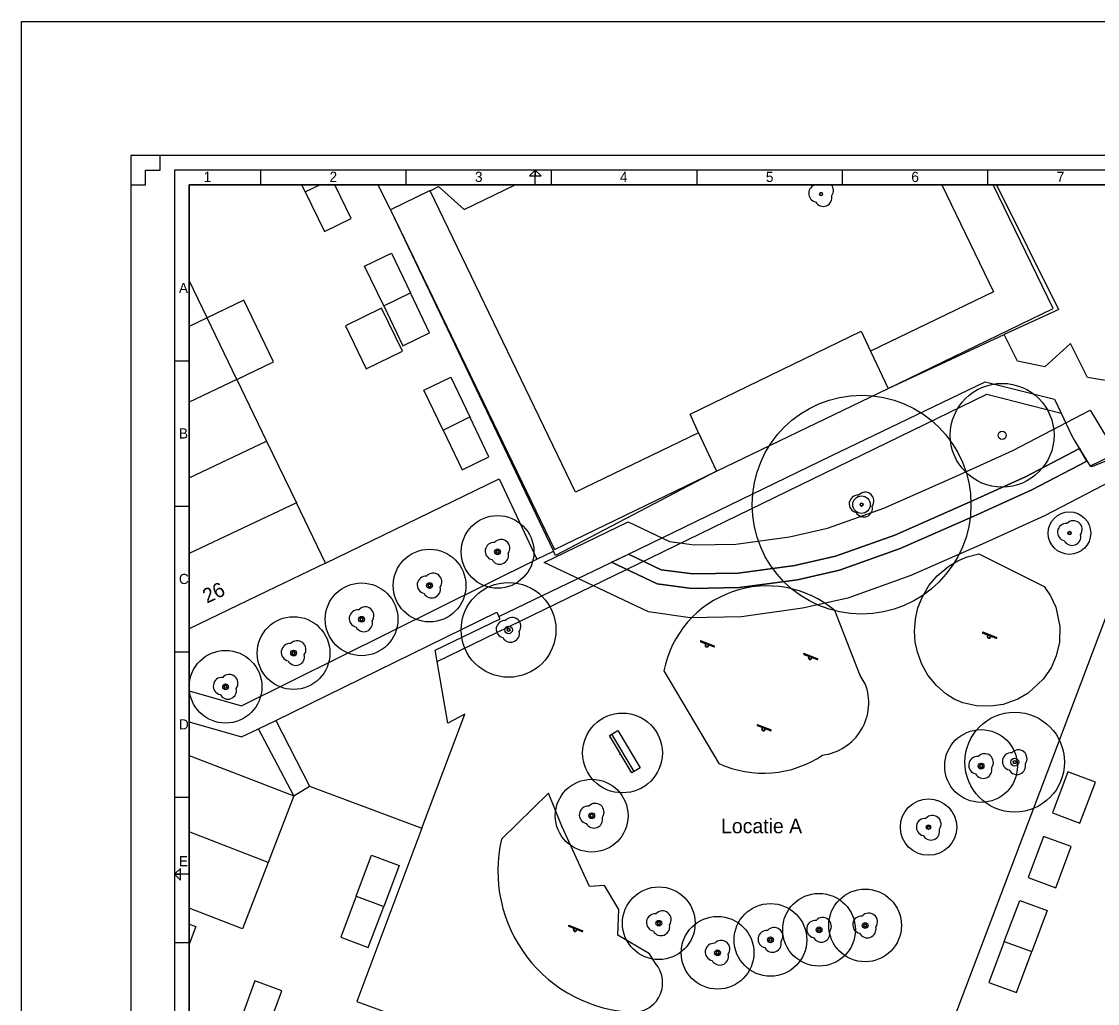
# Model space of a CAD drawing. Extents: x 192664 to 192925, y 446334 to 446521.
# Drawn here: x 192664.2 to 192738.2, y 446453.5 to 446521 of the extents above; entities that cross this region are included whole.
import ezdxf

# ---------------------------------------------------------------- set-up
doc = ezdxf.new("R2010")
doc.units = 0
for name, color, linetype in [('( Toegevoegd 29-11-2021 14_41_42) grens IMGEO maaiveld', 7, 'Continuous'), ('( Toegevoegd 29-11-2021 14_41_42) wegdeel vlak', 7, 'Continuous'), ('1010 viewport', 7, 'Continuous'), ('B-GV-GR-BOOM-S', 7, 'Continuous'), ('B-GV-KG-GRENS_WERKGRENS-G', 7, 'Continuous'), ('boom', 7, 'Continuous'), ('Cultuurscheiding grens', 7, 'Continuous'), ('grens maaiveld', 7, 'Continuous'), ('huisnummerreeks BGT', 7, 'Continuous'), ('kant open verharding', 7, 'Continuous'), ('Luifel', 7, 'Continuous'), ('N-GV-IE-MEUBILAIR_WEGMEUBILAIR_ZITBANK-S', 7, 'Continuous'), ('N-GV-VH-VERHARDING_HALFVERHARDING-G', 7, 'Continuous'), ('pand op maaiveld vlak', 7, 'Continuous'), ('speelvoorziening', 7, 'Continuous'), ('TEKST', 7, 'Continuous'), ('X-XX-AL-TEKENBLAD-S', 7, 'Continuous'), ('X-XX-AL-TEKENBLAD_KADER-G', 7, 'Continuous')]:
    doc.layers.add(name, color=color, linetype=linetype)

msp = doc.modelspace()

# ---------------------------------------------------------------- linework, layer by layer
at = {"layer": '( Toegevoegd 29-11-2021 14_41_42) grens IMGEO maaiveld'}
for points in [[(192692.796, 446476.982), (192700.21, 446480.586), (192706.619, 446483.701), (192730.589, 446495.348), (192735.697, 446494.05)], [(192692.796, 446476.982), (192692.679, 446477.648), (192692.661, 446477.75), (192697.119, 446479.917), (192697.041, 446480.077)]]:
    msp.add_lwpolyline(points, dxfattribs=at)
at = {"layer": '( Toegevoegd 29-11-2021 14_41_42) wegdeel vlak'}
for p, q in [((192723.799, 446495.758), (192731.791, 446499.455)), ((192699.659, 446484.024), (192700.805, 446484.559)), ((192680.513, 446472.341), (192681.713, 446472.935))]:
    msp.add_line(p, q, dxfattribs=at)
for points in [[(192765.561, 446498.667), (192758.023, 446494.654), (192749.243, 446494.562), (192737.517, 446496.509), (192736.353, 446498.833), (192734.578, 446497.242), (192732.701, 446497.637), (192731.791, 446499.455)], [(192697.041, 446480.077), (192705.946, 446484.365), (192719.886, 446491.112), (192730.483, 446496.207), (192735.246, 446495.022), (192735.697, 446494.05)], [(192735.697, 446494.05), (192736.404, 446492.528), (192736.642, 446492.136), (192737.693, 446490.405)], [(192747.709, 446492.058), (192744.573, 446493.06), (192743.573, 446493.255), (192737.693, 446490.405)], [(192712.011, 446490.054), (192700.942, 446484.272), (192700.805, 446484.559)], [(192675.743, 446474.958), (192679.338, 446473.942), (192699.659, 446484.024)], [(192681.713, 446472.935), (192696.889, 446480.371), (192697.041, 446480.077)], [(192675.743, 446472.827), (192679.351, 446471.8), (192680.513, 446472.341)]]:
    msp.add_lwpolyline(points, dxfattribs=at)
at = {"layer": '1010 viewport'}
msp.add_lwpolyline([(192675.743, 446509.756), (192860.643, 446509.756), (192860.643, 446345.556), (192675.743, 446345.556)], close=True, dxfattribs=at)
at = {"layer": 'B-GV-GR-BOOM-S'}
for centre, radius in [((192731.644, 446492.531), 3.567), ((192721.977, 446487.765), 7.524), ((192731.644, 446492.531), 0.285), ((192721.977, 446487.765), 0.602), ((192696.948, 446484.518), 2.5), ((192736.27, 446485.807), 1.46), ((192736.27, 446485.807), 0.117), ((192692.274, 446482.199), 2.5), ((192696.948, 446484.518), 0.2), ((192692.274, 446482.199), 0.2), ((192697.706, 446479.154), 3.258), ((192687.6, 446479.88), 2.5), ((192682.926, 446477.561), 2.5), ((192687.6, 446479.88), 0.2), ((192697.706, 446479.154), 0.261), ((192678.252, 446475.242), 2.5), ((192682.926, 446477.561), 0.2), ((192678.252, 446475.242), 0.2), ((192732.506, 446470.06), 3.428), ((192730.192, 446469.795), 2.5), ((192730.192, 446469.795), 0.2), ((192732.506, 446470.06), 0.274), ((192703.422, 446466.38), 2.5), ((192726.584, 446465.596), 1.938), ((192703.422, 446466.38), 0.2), ((192726.584, 446465.596), 0.155), ((192708.038, 446458.986), 2.5), ((192719.053, 446458.537), 2.5), ((192722.223, 446458.835), 2.5), ((192715.712, 446457.845), 2.5), ((192712.077, 446456.959), 2.5), ((192708.038, 446458.986), 0.2), ((192719.053, 446458.537), 0.2), ((192722.223, 446458.835), 0.2), ((192715.712, 446457.845), 0.2), ((192712.077, 446456.959), 0.2)]:
    msp.add_circle(centre, radius, dxfattribs=at)
at = {"layer": 'B-GV-KG-GRENS_WERKGRENS-G'}
msp.add_lwpolyline([(192740.295, 446489.973), (192734.557, 446486.987), (192730.473, 446485.129), (192725.366, 446482.882), (192721.029, 446481.333), (192717.923, 446480.635), (192713.732, 446480.061), (192710.196, 446479.993), (192707.335, 446480.383), (192700.156, 446483.797), (192705.941, 446486.582), (192708.78, 446485.232), (192710.487, 446485), (192713.343, 446485.054), (192717.034, 446485.56), (192719.635, 446486.145), (192723.516, 446487.53), (192728.43, 446489.693), (192732.367, 446491.484), (192737.694, 446494.256)], close=True, dxfattribs=at)
msp.add_circle((192705.538, 446470.693), 2.743, dxfattribs=at)
at = {"layer": 'boom'}
msp.add_line((192719.898, 446509.756), (192718.831, 446509.756), dxfattribs=at)
for centre in [(192719.192, 446509.116), (192721.977, 446487.765), (192736.298, 446485.811), (192696.948, 446484.518), (192692.274, 446482.199), (192687.6, 446479.88), (192697.706, 446479.154), (192682.926, 446477.561), (192678.252, 446475.242), (192730.192, 446469.795), (192732.506, 446470.06), (192703.422, 446466.38), (192726.595, 446465.551), (192708.038, 446458.986), (192722.223, 446458.835), (192719.053, 446458.537), (192715.712, 446457.845), (192712.077, 446456.959)]:
    msp.add_circle(centre, 0.1, dxfattribs=at)
for centre, radius, start, end in [((192718.942, 446509.166), 0.6, 100.64034, 257.75442), ((192719.442, 446509.366), 0.6, 323.54458, 40.50182), ((192719.192, 446509.116), 0.1, 0, 180), ((192719.192, 446509.116), 0.1, 180, 0), ((192719.342, 446508.866), 0.6, 208.50578, 13.83556), ((192721.727, 446487.815), 0.6, 85.13702, 257.75442), ((192722.227, 446488.015), 0.6, 323.54458, 138.4658), ((192722.127, 446487.515), 0.6, 208.50578, 13.83556), ((192721.977, 446487.765), 0.1, 0, 180), ((192721.977, 446487.765), 0.1, 180, 0), ((192736.048, 446485.861), 0.6, 85.13702, 257.75442), ((192736.548, 446486.061), 0.6, 323.54458, 138.4658), ((192697.198, 446484.768), 0.6, 323.54458, 138.4658), ((192736.448, 446485.561), 0.6, 208.50578, 13.83556), ((192736.298, 446485.811), 0.1, 0, 180), ((192736.298, 446485.811), 0.1, 180, 0), ((192696.698, 446484.568), 0.6, 85.13702, 257.75442), ((192696.948, 446484.518), 0.1, 0, 180), ((192697.098, 446484.268), 0.6, 208.50578, 13.83556), ((192696.948, 446484.518), 0.1, 180, 0), ((192692.024, 446482.249), 0.6, 85.13702, 257.75442), ((192692.524, 446482.449), 0.6, 323.54458, 138.4658), ((192692.424, 446481.949), 0.6, 208.50578, 13.83556), ((192692.274, 446482.199), 0.1, 0, 180), ((192692.274, 446482.199), 0.1, 180, 0), ((192687.35, 446479.93), 0.6, 85.13702, 257.75442), ((192687.85, 446480.13), 0.6, 323.54458, 138.4658), ((192687.75, 446479.63), 0.6, 208.50578, 13.83556), ((192687.6, 446479.88), 0.1, 0, 180), ((192687.6, 446479.88), 0.1, 180, 0), ((192697.456, 446479.204), 0.6, 85.13702, 257.75442), ((192697.956, 446479.404), 0.6, 323.54458, 138.4658), ((192697.856, 446478.904), 0.6, 208.50578, 13.83556), ((192697.706, 446479.154), 0.1, 0, 180), ((192697.706, 446479.154), 0.1, 180, 0), ((192682.676, 446477.611), 0.6, 85.13702, 257.75442), ((192683.176, 446477.811), 0.6, 323.54458, 138.4658), ((192683.076, 446477.311), 0.6, 208.50578, 13.83556), ((192682.926, 446477.561), 0.1, 0, 180), ((192682.926, 446477.561), 0.1, 180, 0), ((192678.002, 446475.292), 0.6, 85.13702, 257.75442), ((192678.502, 446475.492), 0.6, 323.54458, 138.4658), ((192678.402, 446474.992), 0.6, 208.50578, 13.83556), ((192678.252, 446475.242), 0.1, 0, 180), ((192678.252, 446475.242), 0.1, 180, 0), ((192730.442, 446470.045), 0.6, 323.54458, 138.4658), ((192732.256, 446470.11), 0.6, 85.13702, 257.75442), ((192732.756, 446470.31), 0.6, 323.54458, 138.4658), ((192729.942, 446469.845), 0.6, 85.13702, 257.75442), ((192730.192, 446469.795), 0.1, 0, 180), ((192732.656, 446469.81), 0.6, 208.50578, 13.83556), ((192732.506, 446470.06), 0.1, 0, 180), ((192732.506, 446470.06), 0.1, 180, 0), ((192730.342, 446469.545), 0.6, 208.50578, 13.83556), ((192730.192, 446469.795), 0.1, 180, 0), ((192703.172, 446466.43), 0.6, 85.13702, 257.75442), ((192703.672, 446466.63), 0.6, 323.54458, 138.4658), ((192703.572, 446466.13), 0.6, 208.50578, 13.83556), ((192703.422, 446466.38), 0.1, 0, 180), ((192703.422, 446466.38), 0.1, 180, 0), ((192726.345, 446465.601), 0.6, 85.13702, 257.75442), ((192726.845, 446465.801), 0.6, 323.54458, 138.4658), ((192726.745, 446465.301), 0.6, 208.50578, 13.83556), ((192726.595, 446465.551), 0.1, 0, 180), ((192726.595, 446465.551), 0.1, 180, 0), ((192707.788, 446459.036), 0.6, 85.13702, 257.75442), ((192708.288, 446459.236), 0.6, 323.54458, 138.4658), ((192721.973, 446458.885), 0.6, 85.13702, 257.75442), ((192722.473, 446459.085), 0.6, 323.54458, 138.4658), ((192708.188, 446458.736), 0.6, 208.50578, 13.83556), ((192708.038, 446458.986), 0.1, 0, 180), ((192708.038, 446458.986), 0.1, 180, 0), ((192718.803, 446458.587), 0.6, 85.13702, 257.75442), ((192719.303, 446458.787), 0.6, 323.54458, 138.4658), ((192722.373, 446458.585), 0.6, 208.50578, 13.83556), ((192722.223, 446458.835), 0.1, 0, 180), ((192722.223, 446458.835), 0.1, 180, 0), ((192715.462, 446457.895), 0.6, 85.13702, 257.75442), ((192715.962, 446458.095), 0.6, 323.54458, 138.4658), ((192719.203, 446458.287), 0.6, 208.50578, 13.83556), ((192719.053, 446458.537), 0.1, 0, 180), ((192719.053, 446458.537), 0.1, 180, 0), ((192711.827, 446457.009), 0.6, 85.13702, 257.75442), ((192712.327, 446457.209), 0.6, 323.54458, 138.4658), ((192715.862, 446457.595), 0.6, 208.50578, 13.83556), ((192715.712, 446457.845), 0.1, 0, 180), ((192715.712, 446457.845), 0.1, 180, 0), ((192712.227, 446456.709), 0.6, 208.50578, 13.83556), ((192712.077, 446456.959), 0.1, 0, 180), ((192712.077, 446456.959), 0.1, 180, 0)]:
    msp.add_arc(centre, radius, start, end, dxfattribs=at)
at = {"layer": 'Cultuurscheiding grens'}
msp.add_lwpolyline([(192691.747, 446465.52), (192694.691, 446473.369), (192693.538, 446472.733), (192692.796, 446476.982)], dxfattribs=at)
at = {"layer": 'grens maaiveld'}
for p, q in [((192734.733, 446469.332), (192739.028, 446480.658)), ((192708.379, 446476.339), (192712.17, 446469.965)), ((192727.776, 446450.988), (192734.733, 446469.332)), ((192684.027, 446468.415), (192691.747, 446465.52))]:
    msp.add_line(p, q, dxfattribs=at)
for points in [[(192731.256, 446509.756), (192735.523, 446501.181), (192735.241, 446501.05), (192731.791, 446499.455)], [(192689.585, 446508.03), (192698.618, 446489.133), (192700.777, 446484.617), (192700.805, 446484.559)], [(192741.724, 446487.765), (192743.611, 446492.741), (192742.468, 446492.211), (192737.789, 446490.36), (192737.693, 446490.405)], [(192685.115, 446483.75), (192697.057, 446489.535), (192699.659, 446484.024)], [(192730.048, 446484.381), (192734.539, 446482.146), (192734.976, 446481.492), (192735.334, 446480.706), (192735.616, 446479.385), (192735.585, 446478.306), (192735.367, 446477.373), (192735.003, 446476.54), (192734.475, 446475.758), (192733.432, 446474.796), (192732.726, 446474.388), (192731.709, 446474.029), (192730.84, 446473.9), (192729.888, 446473.931), (192728.946, 446474.143), (192728.344, 446474.383), (192727.761, 446474.766), (192727.128, 446475.326), (192726.54, 446476.051), (192726.118, 446476.797), (192725.815, 446477.617), (192725.664, 446478.342), (192725.615, 446479.036), (192725.676, 446479.884), (192725.856, 446480.671), (192726.137, 446481.388), (192726.614, 446482.201), (192727.175, 446482.868), (192727.975, 446483.533), (192728.589, 446483.894), (192729.246, 446484.171), (192730.048, 446484.381)], [(192722.227, 446475.451), (192721.87, 446476.011), (192720.15, 446480.477)], [(192706.331, 446452.863), (192706.518, 446452.877), (192706.732, 446452.916), (192707.023, 446453.007), (192707.362, 446453.181), (192707.672, 446453.423), (192707.87, 446453.641), (192708.021, 446453.863), (192708.159, 446454.143), (192708.26, 446454.473), (192708.295, 446454.703), (192708.29, 446455.149), (192708.241, 446455.406), (192708.137, 446455.709), (192707.986, 446455.995), (192707.816, 446456.224), (192707.394, 446456.89), (192705.222, 446458.158), (192705.296, 446459.943), (192704.312, 446461.578), (192703.272, 446461.519), (192701.368, 446465.65), (192700.45, 446467.928), (192697.225, 446464.769)], [(192691.747, 446465.52), (192687.282, 446453.612), (192695.28, 446450.68)]]:
    msp.add_lwpolyline(points, dxfattribs=at)
for centre, radius, start, end in [((192715.488, 446474.927), 7.248, 49.97203, 168.76539), ((192718.848, 446474.142), 3.624, 277.09196, 21.17996), ((192715.215, 446476.613), 7.313, 245.39293, 303.9147), ((192706.69, 446462.573), 9.716, 166.93585, 267.88344)]:
    msp.add_arc(centre, radius, start, end, dxfattribs=at)
at = {"layer": 'kant open verharding'}
for p, q in [((192681.713, 446472.935), (192684.027, 446468.415)), ((192682.936, 446467.748), (192680.513, 446472.341)), ((192682.936, 446467.748), (192684.027, 446468.415))]:
    msp.add_line(p, q, dxfattribs=at)
at = {"layer": 'Luifel'}
for points in [[(192727.487, 446509.756), (192731.041, 446502.394), (192722.591, 446498.314)], [(192723.799, 446495.758), (192735.147, 446501.237), (192731.034, 446509.756)], [(192710.775, 446492.708), (192702.313, 446488.623), (192692.309, 446509.345)], [(192689.585, 446508.03), (192700.861, 446484.671), (192712.011, 446490.054)], [(192679.03, 446496.364), (192681.55, 446497.579), (192679.505, 446501.819), (192676.985, 446500.604)]]:
    msp.add_lwpolyline(points, dxfattribs=at)
at = {"layer": 'N-GV-IE-MEUBILAIR_WEGMEUBILAIR_ZITBANK-S'}
msp.add_line((192706.336, 446469.418), (192704.802, 446471.996), dxfattribs=at)
msp.add_lwpolyline([(192706.757, 446469.668), (192706.173, 446469.321), (192704.639, 446471.899), (192705.223, 446472.246)], close=True, dxfattribs=at)
for points in [[(192704.741, 446471.727), (192704.711, 446471.709), (192704.685, 446471.753), (192704.716, 446471.771)], [(192705.419, 446470.588), (192705.389, 446470.57), (192705.363, 446470.614), (192705.393, 446470.632)], [(192706.096, 446469.449), (192706.066, 446469.431), (192706.04, 446469.475), (192706.071, 446469.493)]]:
    msp.add_lwpolyline(points, dxfattribs=at)
at = {"layer": 'N-GV-VH-VERHARDING_HALFVERHARDING-G'}
for p, q in [((192737.477, 446490.761), (192736.957, 446491.618)), ((192704.789, 446483.808), (192705.946, 446484.365))]:
    msp.add_line(p, q, dxfattribs=at)
msp.add_lwpolyline([(192737.477, 446490.761), (192733.681, 446488.786), (192729.656, 446486.955), (192724.626, 446484.741), (192720.471, 446483.258), (192717.567, 446482.605), (192713.576, 446482.058), (192710.312, 446481.996), (192707.913, 446482.322), (192704.789, 446483.808), (192705.946, 446484.365), (192708.202, 446483.292), (192710.37, 446482.997), (192713.499, 446483.057), (192717.389, 446483.59), (192720.193, 446484.22), (192724.256, 446485.671), (192729.247, 446487.868), (192733.243, 446489.685), (192736.957, 446491.618)], close=True, dxfattribs=at)
for points in [[(192736.957, 446491.618), (192733.243, 446489.685), (192729.247, 446487.868), (192724.256, 446485.671), (192720.193, 446484.22), (192717.389, 446483.59), (192713.499, 446483.057), (192710.37, 446482.997), (192708.202, 446483.292), (192705.946, 446484.365)], [(192704.789, 446483.808), (192707.913, 446482.322), (192710.312, 446481.996), (192713.576, 446482.058), (192717.567, 446482.605), (192720.471, 446483.258), (192724.626, 446484.741), (192729.656, 446486.955), (192733.681, 446488.786), (192737.477, 446490.761)]]:
    msp.add_lwpolyline(points, dxfattribs=at)
at = {"layer": 'pand op maaiveld vlak'}
for p, q in [((192683.731, 446509.271), (192683.497, 446509.756)), ((192683.731, 446509.271), (192684.724, 446509.756)), ((192689.585, 446508.03), (192688.752, 446509.756)), ((192676.985, 446500.604), (192675.743, 446503.178)), ((192689.125, 446501.419), (192690.963, 446502.317)), ((192676.985, 446500.604), (192675.743, 446500.019)), ((192679.03, 446496.364), (192676.985, 446500.604)), ((192722.591, 446498.314), (192723.799, 446495.758)), ((192679.03, 446496.364), (192675.743, 446494.816)), ((192679.03, 446496.364), (192681.075, 446492.124)), ((192712.011, 446490.054), (192723.799, 446495.758)), ((192693.2, 446492.894), (192695.039, 446493.789)), ((192675.743, 446489.612), (192681.075, 446492.124)), ((192681.075, 446492.124), (192683.121, 446487.884)), ((192710.775, 446492.708), (192712.011, 446490.054)), ((192683.121, 446487.884), (192675.743, 446484.408)), ((192685.115, 446483.75), (192683.121, 446487.884)), ((192682.936, 446467.748), (192681.176, 446463.174)), ((192681.176, 446463.174), (192675.743, 446465.267)), ((192687.232, 446460.852), (192689.122, 446460.139)), ((192731.792, 446457.737), (192733.685, 446457.034))]:
    msp.add_line(p, q, dxfattribs=at)
for points in [[(192683.731, 446509.271), (192685.051, 446506.537), (192686.875, 446507.428), (192685.766, 446509.756)], [(192692.309, 446509.345), (192692.889, 446509.625), (192694.656, 446508.062), (192698.165, 446509.756)], [(192692.309, 446509.345), (192692.269, 446509.326), (192689.585, 446508.03)], [(192689.125, 446501.419), (192687.803, 446504.152), (192689.654, 446505.056), (192690.963, 446502.317)], [(192689.125, 446501.419), (192690.447, 446498.686), (192692.271, 446499.578), (192690.963, 446502.317)], [(192687.914, 446497.106), (192690.409, 446498.313), (192688.979, 446501.269), (192686.484, 446500.062), (192687.914, 446497.106)], [(192710.775, 446492.708), (192710.185, 446493.976), (192721.945, 446499.683), (192722.591, 446498.314)], [(192693.2, 446492.894), (192691.882, 446495.629), (192693.735, 446496.53), (192695.039, 446493.789)], [(192693.2, 446492.894), (192694.518, 446490.159), (192696.343, 446491.047), (192695.039, 446493.789)], [(192685.115, 446483.75), (192681.106, 446481.808), (192675.743, 446479.221)], [(192675.743, 446470.516), (192678.718, 446469.371), (192682.936, 446467.748)], [(192735.101, 446466.567), (192736.994, 446465.863), (192738.058, 446468.69), (192736.166, 446469.393), (192735.101, 446466.567)], [(192734.497, 446464.956), (192733.437, 446462.128), (192735.331, 446461.425), (192736.391, 446464.253), (192734.497, 446464.956)], [(192681.176, 446463.174), (192679.42, 446458.61), (192675.743, 446460.024)], [(192687.232, 446460.852), (192688.294, 446463.668), (192690.184, 446462.955), (192689.122, 446460.139)], [(192687.232, 446460.852), (192686.17, 446458.035), (192688.06, 446457.322), (192689.122, 446460.139)], [(192731.792, 446457.737), (192732.848, 446460.555), (192734.741, 446459.852), (192733.685, 446457.034)], [(192675.743, 446458.935), (192676.203, 446458.762), (192675.743, 446457.539)], [(192731.792, 446457.737), (192730.735, 446454.918), (192732.628, 446454.215), (192733.685, 446457.034)], [(192681.074, 446451.51), (192682.119, 446454.348), (192680.269, 446455.029), (192679.224, 446452.192)]]:
    msp.add_lwpolyline(points, dxfattribs=at)
at = {"layer": 'speelvoorziening'}
for p, q in [((192730.309, 446478.935), (192730.671, 446478.795)), ((192731.252, 446478.634), (192730.331, 446478.99)), ((192730.851, 446478.725), (192731.231, 446478.578)), ((192710.914, 446478.335), (192711.276, 446478.195)), ((192711.857, 446478.034), (192710.936, 446478.39)), ((192711.456, 446478.125), (192711.836, 446477.978)), ((192718.013, 446477.47), (192718.375, 446477.33)), ((192718.956, 446477.169), (192718.035, 446477.525)), ((192718.555, 446477.26), (192718.935, 446477.113)), ((192714.806, 446472.575), (192715.168, 446472.435)), ((192715.749, 446472.274), (192714.828, 446472.63)), ((192715.348, 446472.365), (192715.728, 446472.218)), ((192701.855, 446458.775), (192702.217, 446458.635)), ((192702.798, 446458.474), (192701.877, 446458.83)), ((192702.397, 446458.565), (192702.777, 446458.418))]:
    msp.add_line(p, q, dxfattribs=at)
for centre in [(192730.736, 446478.695), (192711.341, 446478.095), (192718.44, 446477.23), (192715.233, 446472.335), (192702.282, 446458.535)]:
    msp.add_circle(centre, 0.1, dxfattribs=at)
for centre, radius, start, end in [((192730.32, 446478.963), 0.0297, 68.83874, 248.83874), ((192730.736, 446478.695), 0.119, 123.04996, 14.62752), ((192730.736, 446478.695), 0.1, 0, 180), ((192730.736, 446478.695), 0.1, 180, 0), ((192710.925, 446478.363), 0.0297, 68.83874, 248.83874), ((192711.341, 446478.095), 0.119, 123.04996, 14.62752), ((192711.341, 446478.095), 0.1, 0, 180), ((192711.341, 446478.095), 0.1, 180, 0), ((192711.846, 446478.006), 0.0297, 248.83874, 68.83874), ((192731.241, 446478.606), 0.0297, 248.83874, 68.83874), ((192718.024, 446477.498), 0.0297, 68.83874, 248.83874), ((192718.44, 446477.23), 0.119, 123.04996, 14.62752), ((192718.44, 446477.23), 0.1, 0, 180), ((192718.44, 446477.23), 0.1, 180, 0), ((192718.945, 446477.141), 0.0297, 248.83874, 68.83874), ((192714.817, 446472.603), 0.0297, 68.83874, 248.83874), ((192715.233, 446472.335), 0.119, 123.04996, 14.62752), ((192715.233, 446472.335), 0.1, 0, 180), ((192715.233, 446472.335), 0.1, 180, 0), ((192715.738, 446472.246), 0.0297, 248.83874, 68.83874), ((192701.866, 446458.803), 0.0297, 68.83874, 248.83874), ((192702.282, 446458.535), 0.119, 123.04996, 14.62752), ((192702.282, 446458.535), 0.1, 0, 180), ((192702.282, 446458.535), 0.1, 180, 0), ((192702.787, 446458.446), 0.0297, 248.83874, 68.83874)]:
    msp.add_arc(centre, radius, start, end, dxfattribs=at)
at = {"layer": 'X-XX-AL-TEKENBLAD-S'}
for p, q in [((192909.543, 446511.756), (192671.743, 446511.756)), ((192671.743, 446511.756), (192671.743, 446343.556)), ((192908.543, 446510.756), (192674.743, 446510.756)), ((192674.743, 446510.756), (192674.743, 446344.556)), ((192680.643, 446510.756), (192680.643, 446509.756)), ((192690.643, 446510.756), (192690.643, 446509.756)), ((192699.543, 446509.756), (192699.543, 446510.756)), ((192700.643, 446510.756), (192700.643, 446509.756)), ((192710.643, 446510.756), (192710.643, 446509.756)), ((192720.643, 446510.756), (192720.643, 446509.756)), ((192730.643, 446510.756), (192730.643, 446509.756)), ((192674.743, 446497.656), (192675.743, 446497.656)), ((192674.743, 446487.656), (192675.743, 446487.656)), ((192674.743, 446477.656), (192675.743, 446477.656)), ((192674.743, 446467.656), (192675.743, 446467.656)), ((192675.143, 446462.356), (192674.743, 446462.356)), ((192674.743, 446462.356), (192675.143, 446462.356)), ((192675.743, 446462.356), (192674.743, 446462.356)), ((192674.743, 446457.656), (192675.743, 446457.656))]:
    msp.add_line(p, q, dxfattribs=at)
for points in [[(192673.743, 446511.756), (192671.743, 446511.756), (192671.743, 446509.756), (192672.743, 446509.756), (192672.743, 446510.756), (192673.743, 446510.756), (192673.743, 446511.756)], [(192699.543, 446510.356), (192699.543, 446510.756), (192699.143, 446510.356), (192699.543, 446510.356)], [(192699.543, 446510.756), (192699.543, 446510.356), (192699.943, 446510.356), (192699.543, 446510.756)], [(192675.143, 446462.356), (192675.143, 446462.756), (192674.743, 446462.356)], [(192674.743, 446462.356), (192675.143, 446461.956), (192675.143, 446462.356)]]:
    msp.add_lwpolyline(points, dxfattribs=at)
msp.add_lwpolyline([(192675.743, 446345.556), (192907.543, 446345.556), (192907.543, 446509.756), (192675.743, 446509.756)], close=True, dxfattribs=at)
at = {"layer": 'X-XX-AL-TEKENBLAD_KADER-G'}
msp.add_lwpolyline([(192664.22, 446520.974), (192925.029, 446520.974), (192925.029, 446333.894), (192664.22, 446333.894)], close=True, dxfattribs=at)

# ---------------------------------------------------------------- texts
at = {"layer": 'huisnummerreeks BGT'}
msp.add_text('26', height=1, rotation=25.2, dxfattribs=at).set_placement((192676.963, 446480.952))
at = {"layer": 'TEKST'}
msp.add_text('Locatie A', height=1, dxfattribs=at).set_placement((192712.316, 446465.173))
at = {"layer": 'X-XX-AL-TEKENBLAD-S'}
for s, p in [('1', (192676.745, 446509.945)), ('2', (192685.399, 446509.945)), ('3', (192695.398, 446509.945)), ('4', (192705.364, 446509.945)), ('5', (192715.399, 446509.945)), ('6', (192725.399, 446509.945)), ('7', (192735.399, 446509.945)), ('A', (192675.043, 446502.306)), ('B', (192675.043, 446492.306)), ('C', (192675.043, 446482.306)), ('D', (192675.043, 446472.306)), ('E', (192675.043, 446462.906))]:
    msp.add_text(s, height=0.7, dxfattribs=at).set_placement(p)

doc.saveas('drawing.dxf')
